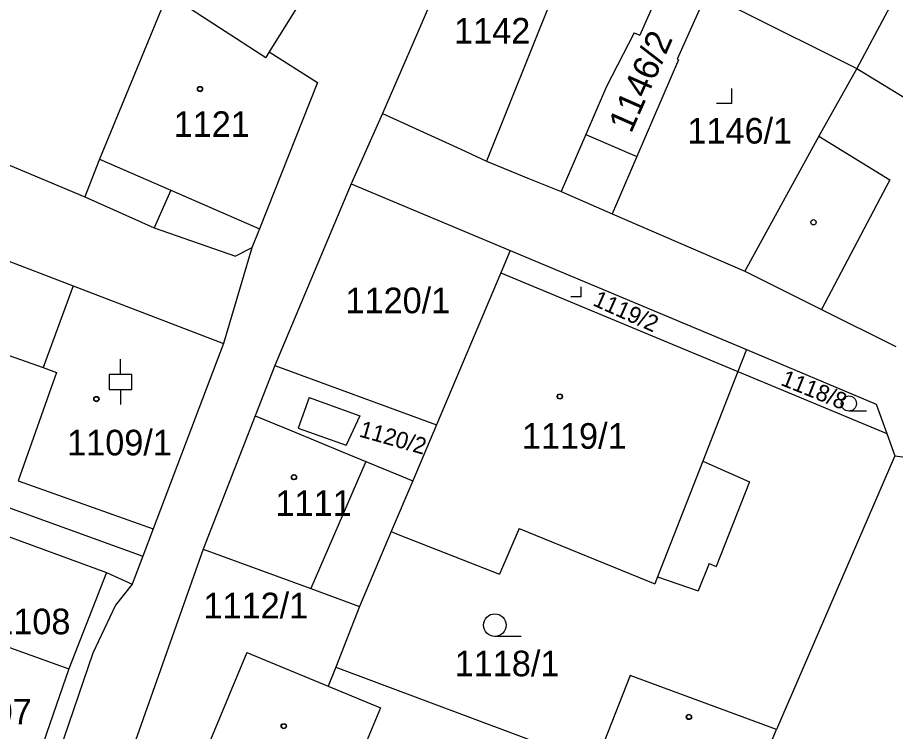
# Model space of a CAD drawing. Extents: x -593183 to -588034, y -1130415 to -1124994.
# Drawn here: x -591094.9 to -591036.6, y -1128971.4 to -1128924 of the extents above; entities that cross this region are included whole.
import ezdxf

# ---------------------------------------------------------------- set-up
doc = ezdxf.new("R2010")
doc.units = 0
for name, color, linetype in [('Vrstva 1', 7, 'Continuous'), ('Vrstva 18', 7, 'Continuous'), ('Vrstva 19', 7, 'Continuous'), ('Vrstva 25', 7, 'Continuous'), ('Vrstva 4', 7, 'Continuous')]:
    doc.layers.add(name, color=color, linetype=linetype)

msp = doc.modelspace()

# ---------------------------------------------------------------- linework, layer by layer
at = {"layer": 'Vrstva 1'}
for p, q in [((-591031.44, -1128912.87), (-591039.19, -1128927.37)), ((-591064.46, -1128915.98), (-591070.68, -1128930.35)), ((-591049.94, -1128916.85), (-591053.58, -1128925.15)), ((-591047.21, -1128918.09), (-591051.12, -1128926.74)), ((-591074.83, -1128920.84), (-591078.2, -1128926.25)), ((-591058.7, -1128920.84), (-591063.76, -1128933.51)), ((-591084.94, -1128922.4), (-591078.43, -1128926.63)), ((-591047.09, -1128923.42), (-591039.19, -1128927.37)), ((-591053.97, -1128924.99), (-591055.8, -1128928.57)), ((-591053.97, -1128924.99), (-591053.58, -1128925.15)), ((-591078.2, -1128926.25), (-591078.43, -1128926.63)), ((-591078.2, -1128926.25), (-591074.99, -1128928.29)), ((-591051.12, -1128926.74), (-591051.03, -1128926.78)), ((-591051.03, -1128926.78), (-591053.79, -1128933.21)), ((-591039.19, -1128927.37), (-591041.71, -1128931.87)), ((-591074.99, -1128928.29), (-591078.85, -1128938.01)), ((-591055.8, -1128928.57), (-591057.18, -1128931.76)), ((-591070.68, -1128930.35), (-591072.75, -1128935.02)), ((-591070.68, -1128930.35), (-591066.5, -1128932.26)), ((-591057.18, -1128931.76), (-591058.81, -1128935.54)), ((-591057.18, -1128931.76), (-591056.82, -1128931.91)), ((-591056.82, -1128931.91), (-591053.79, -1128933.21)), ((-591041.71, -1128931.87), (-591046.61, -1128940.82)), ((-591066.5, -1128932.26), (-591065.47, -1128932.73)), ((-591098.01, -1128932.7), (-591090.43, -1128935.9)), ((-591065.47, -1128932.73), (-591063.76, -1128933.51)), ((-591063.76, -1128933.51), (-591061.02, -1128934.66)), ((-591061.02, -1128934.66), (-591058.81, -1128935.54)), ((-591072.75, -1128935.02), (-591077.82, -1128947.1)), ((-591072.75, -1128935.02), (-591062.19, -1128939.46)), ((-591090.43, -1128935.9), (-591085.84, -1128937.95)), ((-591058.81, -1128935.54), (-591055.42, -1128937.01)), ((-591055.42, -1128937.01), (-591046.61, -1128940.82)), ((-591085.84, -1128937.95), (-591080.43, -1128939.84)), ((-591078.85, -1128938.01), (-591079.35, -1128939.28)), ((-591079.35, -1128939.28), (-591081.24, -1128945.62)), ((-591079.35, -1128939.28), (-591080.43, -1128939.84)), ((-591062.19, -1128939.46), (-591062.82, -1128940.94)), ((-591062.19, -1128939.46), (-591046.51, -1128946.03)), ((-591096.05, -1128939.94), (-591091.21, -1128941.8)), ((-591062.82, -1128940.94), (-591067.09, -1128951.04)), ((-591062.82, -1128940.94), (-591047.08, -1128947.49)), ((-591046.61, -1128940.82), (-591041.54, -1128943.37)), ((-591091.21, -1128941.8), (-591081.24, -1128945.62)), ((-591041.54, -1128943.37), (-591036.59, -1128945.84)), ((-591081.24, -1128945.62), (-591085.9, -1128957.94)), ((-591046.51, -1128946.03), (-591047.08, -1128947.49)), ((-591046.51, -1128946.03), (-591037.89, -1128949.67)), ((-591077.82, -1128947.1), (-591079.12, -1128950.43)), ((-591077.82, -1128947.1), (-591067.09, -1128951.04)), ((-591047.08, -1128947.49), (-591049.41, -1128953.45)), ((-591047.08, -1128947.49), (-591037.19, -1128951.61)), ((-591037.89, -1128949.67), (-591037.19, -1128951.61)), ((-591079.12, -1128950.43), (-591082.57, -1128959.29)), ((-591079.12, -1128950.43), (-591076.69, -1128951.44)), ((-591067.09, -1128951.04), (-591068.66, -1128954.76)), ((-591076.69, -1128951.44), (-591073.29, -1128952.84)), ((-591037.19, -1128951.61), (-591036.65, -1128953.09)), ((-591073.29, -1128952.84), (-591071.79, -1128953.46)), ((-591071.79, -1128953.46), (-591068.66, -1128954.76)), ((-591049.41, -1128953.45), (-591046.31, -1128954.81)), ((-591036.65, -1128953.09), (-591044.51, -1128971.27)), ((-591036.65, -1128953.09), (-591021.77, -1128955.01)), ((-591068.66, -1128954.76), (-591070.1, -1128958.12)), ((-591046.31, -1128954.81), (-591048.53, -1128960.43)), ((-591096.71, -1128956.08), (-591086.59, -1128959.76)), ((-591096.73, -1128958), (-591088.99, -1128960.83)), ((-591085.9, -1128957.94), (-591086.59, -1128959.76)), ((-591070.1, -1128958.12), (-591072.2, -1128963.09)), ((-591070.1, -1128958.12), (-591069.63, -1128958.31)), ((-591061.6, -1128957.91), (-591062.91, -1128960.96)), ((-591061.6, -1128957.91), (-591052.59, -1128961.59)), ((-591069.63, -1128958.31), (-591062.91, -1128960.96)), ((-591082.57, -1128959.29), (-591087.52, -1128973.28)), ((-591082.57, -1128959.29), (-591075.43, -1128961.91)), ((-591086.59, -1128959.76), (-591087.29, -1128961.61)), ((-591048.99, -1128960.25), (-591049.71, -1128962.06)), ((-591048.99, -1128960.25), (-591048.53, -1128960.43)), ((-591088.99, -1128960.83), (-591091.5, -1128967.24)), ((-591088.99, -1128960.83), (-591087.29, -1128961.61)), ((-591052.41, -1128961.12), (-591052.59, -1128961.59)), ((-591052.41, -1128961.12), (-591049.71, -1128962.06)), ((-591075.43, -1128961.91), (-591072.2, -1128963.09)), ((-591072.2, -1128963.09), (-591073.78, -1128967.13)), ((-591099.09, -1128964.52), (-591091.5, -1128967.24)), ((-591079.68, -1128966.15), (-591083.27, -1128974.76)), ((-591079.68, -1128966.15), (-591074.29, -1128968.39)), ((-591091.5, -1128967.24), (-591093.68, -1128973.55)), ((-591073.78, -1128967.13), (-591074.29, -1128968.39)), ((-591073.78, -1128967.13), (-591047.03, -1128977.11)), ((-591054.24, -1128967.67), (-591056.33, -1128973.04)), ((-591044.51, -1128971.27), (-591054.24, -1128967.67)), ((-591074.29, -1128968.39), (-591070.81, -1128969.83)), ((-591070.81, -1128969.83), (-591074.46, -1128978.6)), ((-591046.85, -1128976.69), (-591044.51, -1128971.27))]:
    msp.add_line(p, q, dxfattribs=at)
at = {"layer": 'Vrstva 25'}
for p, q in [((-591047.49, -1128929.7), (-591047.49, -1128928.7)), ((-591047.49, -1128929.7), (-591048.49, -1128929.7)), ((-591057.49, -1128942.53), (-591057.49, -1128941.86)), ((-591057.49, -1128942.53), (-591058.16, -1128942.53)), ((-591088.07, -1128947.68), (-591088.07, -1128946.68)), ((-591088.07, -1128948.68), (-591088.07, -1128949.68)), ((-591038.537, -1128950.12), (-591039.71, -1128950.12)), ((-591061.47, -1128965.08), (-591063.22, -1128965.08))]:
    msp.add_line(p, q, dxfattribs=at)
msp.add_lwpolyline([(-591088.82, -1128948.68), (-591087.32, -1128948.68), (-591087.32, -1128947.68), (-591088.82, -1128947.68)], close=True, dxfattribs=at)
for centre, radius in [((-591082.79, -1128928.73), 0.175), ((-591082.79, -1128928.73), 0.15), ((-591042.06, -1128937.58), 0.175), ((-591089.67, -1128949.32), 0.175), ((-591089.67, -1128949.32), 0.15), ((-591058.9, -1128949.15), 0.175), ((-591058.9, -1128949.15), 0.15), ((-591039.71, -1128949.618), 0.503), ((-591076.55, -1128954.51), 0.175), ((-591076.55, -1128954.51), 0.15), ((-591063.22, -1128964.33), 0.75), ((-591050.33, -1128970.43), 0.175), ((-591050.33, -1128970.43), 0.15), ((-591077.23, -1128971.04), 0.175), ((-591077.23, -1128971.04), 0.15)]:
    msp.add_circle(centre, radius, dxfattribs=at)
at = {"layer": 'Vrstva 4'}
for p, q in [((-591084.94, -1128922.4), (-591089.47, -1128933.39)), ((-591039.19, -1128927.37), (-591032.18, -1128931.66)), ((-591041.71, -1128931.87), (-591036.99, -1128934.77)), ((-591089.47, -1128933.39), (-591090.43, -1128935.9)), ((-591089.47, -1128933.39), (-591084.73, -1128935.45)), ((-591053.79, -1128933.21), (-591055.14, -1128936.35)), ((-591036.99, -1128934.77), (-591041.54, -1128943.37)), ((-591084.73, -1128935.45), (-591085.84, -1128937.95)), ((-591084.73, -1128935.45), (-591078.85, -1128938.01)), ((-591055.14, -1128936.35), (-591055.42, -1128937.01)), ((-591091.21, -1128941.8), (-591093.21, -1128947.23)), ((-591095.53, -1128946.41), (-591093.21, -1128947.23)), ((-591092.31, -1128947.55), (-591094.87, -1128954.76)), ((-591093.21, -1128947.23), (-591092.31, -1128947.55)), ((-591075.54, -1128949.22), (-591076.27, -1128951.25)), ((-591075.54, -1128949.22), (-591072.17, -1128950.43)), ((-591072.17, -1128950.43), (-591073.08, -1128952.38)), ((-591076.27, -1128951.25), (-591073.08, -1128952.38)), ((-591071.79, -1128953.46), (-591075.43, -1128961.91)), ((-591049.41, -1128953.45), (-591052.41, -1128961.12)), ((-591094.87, -1128954.76), (-591085.9, -1128957.94)), ((-591087.29, -1128961.61), (-591088.41, -1128963.01)), ((-591088.41, -1128963.01), (-591089.91, -1128966.19)), ((-591089.91, -1128966.19), (-591117, -1129045.34))]:
    msp.add_line(p, q, dxfattribs=at)

# ---------------------------------------------------------------- texts
at = {"layer": 'Vrstva 18'}
for s, p in [('1120/1', (-591073.13, -1128943.62)), ('1112/1', (-591082.56, -1128963.88)), ('1118/1', (-591065.88, -1128967.73))]:
    msp.add_text(s, height=1.7, dxfattribs=at).set_placement(p)
for s, rotation, p in [('1118/8', 338.09121, (-591044.3, -1128948.37)), ('1120/2', 344.25324, (-591072.28, -1128951.8))]:
    msp.add_text(s, height=1.1, rotation=rotation, dxfattribs=at).set_placement(p)
at = {"layer": 'Vrstva 19'}
for s, p in [('1142', (-591065.92, -1128925.71)), ('1121', (-591084.54, -1128931.91)), ('1146/1', (-591050.43, -1128932.35)), ('1119/1', (-591061.42, -1128952.62)), ('1109/1', (-591091.61, -1128953.06)), ('1111', (-591077.78, -1128957.08)), ('1108', (-591096.45, -1128964.94)), ('1107', (-591099.02, -1128970.93))]:
    msp.add_text(s, height=1.7, dxfattribs=at).set_placement(p)
for s, height, rotation, p in [('1146/2', 1.7, 66.26772, (-591054.17, -1128931.73)), ('1119/2', 1.1, 335.87451, (-591056.78, -1128943.07))]:
    msp.add_text(s, height=height, rotation=rotation, dxfattribs=at).set_placement(p)

doc.saveas('drawing.dxf')
